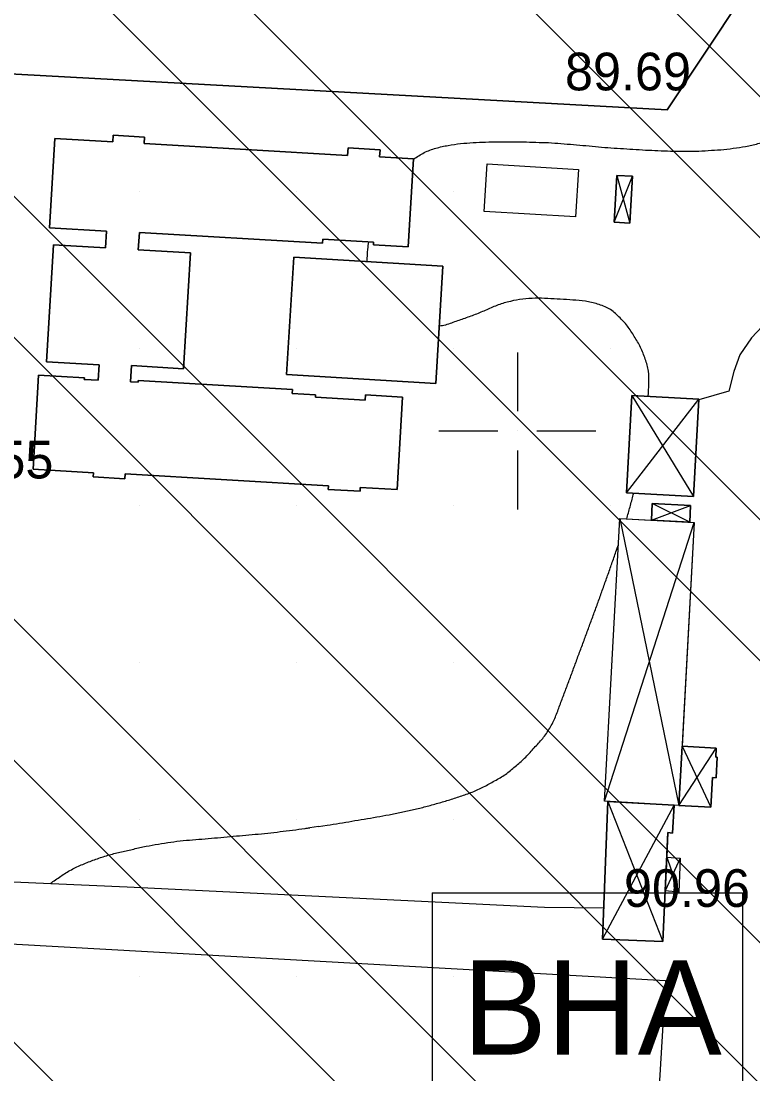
# Model space of a CAD drawing. Extents: x 417995 to 421451, y 4454518 to 4458015.
# Drawn here: x 420920.9 to 421037.5, y 4455397.6 to 4455565.3 of the extents above; entities that cross this region are included whole.
import ezdxf

# ---------------------------------------------------------------- set-up
doc = ezdxf.new("R2010")
doc.units = 0
for name, color, linetype in [('ADAKENARI', 7, 'Continuous'), ('B_Betonzemin', 7, 'Continuous'), ('B_Sundurma', 7, 'Continuous'), ('B_Ticari', 7, 'Continuous'), ('Egri_1m', 7, 'Continuous'), ('P_Grid', 7, 'Continuous'), ('PL_K_BHA', 7, 'Continuous'), ('PL_SAY_KULTUR_TESIS', 7, 'Continuous'), ('SEMBOL_FAT', 7, 'Continuous'), ('SN_TR_SIVILASMA', 7, 'Continuous'), ('TRFAT_BHA', 7, 'Continuous'), ('Y_Kot_Noktasi', 7, 'Continuous')]:
    doc.layers.add(name, color=color, linetype=linetype)

msp = doc.modelspace()

# ---------------------------------------------------------------- linework, layer by layer
at = {"layer": 'ADAKENARI'}
for p, q in [((421023.86, 4455551.11), (421062.73, 4455609.79)), ((420910.3, 4455557.31), (421023.86, 4455551.11))]:
    msp.add_line(p, q, dxfattribs=at)
at = {"layer": 'B_Betonzemin'}
for points in [[(421095.31, 4455422.46), (421065.35, 4455422.26), (421044.81, 4455422.44), (421046.68, 4455456.53), (421048.17, 4455479.85), (421049.52, 4455500.17), (421050.69, 4455507.83), (421055.38, 4455517.65), (421063.57, 4455528.36), (421074.27, 4455541.53), (421066.68, 4455548.25), (421047.77, 4455525.92), (421037.29, 4455514.83), (421035.41, 4455512.12), (421034.49, 4455509.46), (421033.69, 4455506.32), (421028.89, 4455504.93)], [(420995.2, 4455542.55), (421009.72, 4455541.64), (421009.24, 4455534.06), (420994.72, 4455534.96), (420995.2, 4455542.55)], [(420901, 4455380.01), (420934.43, 4455378.05), (420936.03, 4455378.69), (420936.55, 4455379.4), (420936.66, 4455380.27), (420936.46, 4455381.12), (420936.06, 4455381.79), (420935.35, 4455382.61), (420934.47, 4455382.85), (420932.54, 4455383.01), (420905.31, 4455384.24), (420907.36, 4455422.42), (420907.52, 4455428.73), (420937.87, 4455427.42), (421004.34, 4455424.16), (421013.77, 4455424.08)]]:
    msp.add_lwpolyline(points, dxfattribs=at)
at = {"layer": 'B_Sundurma'}
for p, q in [((421015.4, 4455533.24), (421018.35, 4455540.55)), ((421015.82, 4455540.69), (421017.94, 4455533.1)), ((421017.36, 4455490.13), (421028.9, 4455505.06)), ((421018.22, 4455505.65), (421028.04, 4455489.54)), ((421021.35, 4455485.78), (421027.6, 4455488.13)), ((421027.46, 4455485.45), (421021.49, 4455488.46)), ((421016.32, 4455486.05), (421025.73, 4455440.39)), ((421013.9, 4455441.03), (421028.14, 4455485.41)), ((421025.73, 4455440.39), (421031.68, 4455449.51)), ((421026.23, 4455449.8), (421030.81, 4455440.12)), ((421013.57, 4455419.1), (421024.96, 4455440.43)), ((421014.43, 4455441), (421023.15, 4455418.72)), ((421025.94, 4455432), (421023.54, 4455426.78)), ((421023.8, 4455432.16), (421025.71, 4455426.59))]:
    msp.add_line(p, q, dxfattribs=at)
for points in [[(421015.82, 4455540.69), (421015.4, 4455533.24), (421017.94, 4455533.1), (421018.35, 4455540.55)], [(421015.82, 4455540.69), (421018.35, 4455540.55), (421017.94, 4455533.1), (421015.4, 4455533.24)], [(421018.22, 4455505.65), (421017.36, 4455490.13), (421028.04, 4455489.54), (421028.9, 4455505.06)], [(421018.22, 4455505.65), (421028.9, 4455505.06), (421028.04, 4455489.54), (421017.36, 4455490.13)], [(421021.35, 4455485.78), (421027.46, 4455485.45), (421027.6, 4455488.13), (421021.49, 4455488.46)], [(421021.35, 4455485.78), (421021.49, 4455488.46), (421027.6, 4455488.13), (421027.46, 4455485.45)], [(421013.9, 4455441.03), (421016.32, 4455486.05), (421028.14, 4455485.41), (421025.73, 4455440.39)], [(421021.35, 4455485.78), (421027.46, 4455485.45), (421028.14, 4455485.41), (421026.24, 4455449.8), (421025.73, 4455440.39), (421024.96, 4455440.43), (421014.43, 4455441), (421013.9, 4455441.03), (421016.32, 4455486.05)], [(421026.23, 4455449.8), (421025.73, 4455440.39), (421030.81, 4455440.12), (421031.06, 4455444.82), (421031.67, 4455444.79), (421031.85, 4455448.07), (421031.61, 4455448.08), (421031.68, 4455449.51)], [(421025.73, 4455440.39), (421026.24, 4455449.8), (421031.68, 4455449.51), (421031.61, 4455448.08), (421031.85, 4455448.07), (421031.67, 4455444.79), (421031.06, 4455444.82), (421030.81, 4455440.12)], [(421014.43, 4455441), (421013.57, 4455419.1), (421023.15, 4455418.72), (421023.99, 4455436.04), (421024.71, 4455435.98), (421024.96, 4455440.43)], [(421024.96, 4455440.43), (421024.71, 4455435.98), (421023.99, 4455436.04), (421023.8, 4455432.16), (421023.54, 4455426.78), (421023.15, 4455418.72), (421013.57, 4455419.1), (421014.43, 4455441)], [(421023.8, 4455432.16), (421025.94, 4455432), (421025.71, 4455426.59), (421023.54, 4455426.78)], [(421023.54, 4455426.78), (421023.8, 4455432.16), (421025.94, 4455432), (421025.71, 4455426.59)]]:
    msp.add_lwpolyline(points, close=True, dxfattribs=at)
at = {"layer": 'B_Ticari'}
for points in [[(420923.73, 4455508.86), (420922.85, 4455493.92), (420932.46, 4455493.35), (420932.42, 4455492.68), (420937.5, 4455492.38), (420937.55, 4455493.17), (420969.92, 4455491.25), (420969.89, 4455490.69), (420974.95, 4455490.39), (420974.98, 4455491.01), (420980.84, 4455490.67), (420981.71, 4455505.39), (420975.79, 4455505.74), (420975.74, 4455504.9), (420967.82, 4455505.37), (420967.84, 4455505.76), (420964.15, 4455505.98), (420964.19, 4455506.6), (420939.6, 4455508.05), (420939.58, 4455507.74), (420938.38, 4455507.81), (420938.53, 4455510.39), (420946.82, 4455509.9), (420947.91, 4455528.35), (420939.62, 4455528.84), (420939.79, 4455531.59), (420968.97, 4455529.87), (420969.01, 4455530.51), (420977.11, 4455530.03), (420977.09, 4455529.64), (420982.62, 4455529.32), (420983.45, 4455543.33), (420978.06, 4455543.65), (420978.13, 4455544.77), (420973.03, 4455545.07), (420972.95, 4455543.83), (420940.57, 4455545.75), (420940.63, 4455546.77), (420935.62, 4455547.07), (420935.56, 4455546.01), (420926.32, 4455546.56), (420925.48, 4455532.32), (420934.56, 4455531.78), (420934.4, 4455529.13), (420926.11, 4455529.62), (420925.01, 4455511.01), (420933.37, 4455510.52), (420933.22, 4455508.06), (420931.01, 4455508.19), (420931.03, 4455508.43)], [(420923.73, 4455508.86), (420931.03, 4455508.43), (420931.01, 4455508.19), (420933.22, 4455508.06), (420933.37, 4455510.52), (420925.01, 4455511.01), (420926.11, 4455529.62), (420934.4, 4455529.13), (420934.56, 4455531.78), (420925.48, 4455532.32), (420926.32, 4455546.56), (420935.56, 4455546.01), (420935.62, 4455547.07), (420940.63, 4455546.77), (420940.57, 4455545.75), (420972.95, 4455543.83), (420973.03, 4455545.07), (420978.13, 4455544.77), (420978.06, 4455543.65), (420983.45, 4455543.33), (420982.62, 4455529.32), (420977.09, 4455529.64), (420977.11, 4455530.03), (420969.01, 4455530.51), (420968.97, 4455529.87), (420939.79, 4455531.59), (420939.62, 4455528.84), (420947.91, 4455528.35), (420946.82, 4455509.9), (420938.53, 4455510.39), (420938.38, 4455507.81), (420939.58, 4455507.74), (420939.6, 4455508.05), (420964.19, 4455506.6), (420964.15, 4455505.98), (420967.84, 4455505.76), (420967.82, 4455505.37), (420975.74, 4455504.9), (420975.79, 4455505.74), (420981.71, 4455505.39), (420980.84, 4455490.67), (420974.98, 4455491.01), (420974.95, 4455490.39), (420969.89, 4455490.69), (420969.92, 4455491.25), (420937.55, 4455493.17), (420937.5, 4455492.38), (420932.42, 4455492.68), (420932.46, 4455493.35), (420922.85, 4455493.92)], [(420988.12, 4455526.21), (420964.37, 4455527.64), (420963.25, 4455508.97), (420987, 4455507.54)], [(420988.12, 4455526.21), (420987, 4455507.54), (420963.25, 4455508.97), (420964.37, 4455527.64)], [(420913.52, 4455418.68), (421023.6, 4455412.5), (421022.26, 4455390.39), (420912.46, 4455396.44)], [(420913.52, 4455418.68), (421023.6, 4455412.5), (421022.26, 4455390.39), (420912.46, 4455396.44)]]:
    msp.add_lwpolyline(points, close=True, dxfattribs=at)
at = {"layer": 'Egri_1m'}
for q in [(420966.95, 4455436.83), (420969.7, 4455437.23)]:
    msp.add_line((420968.32, 4455437.03), q, dxfattribs=at)
for points in [[(420983.44, 4455543.28), (420985.16, 4455544.31), (420987.03, 4455545.02), (420988.98, 4455545.46), (420990.96, 4455545.74), (420992.95, 4455545.9), (420994.95, 4455545.99), (420996.95, 4455546.02), (420998.95, 4455546.03), (421000.95, 4455546.03), (421002.95, 4455545.96), (421004.95, 4455545.9), (421006.94, 4455545.76), (421008.94, 4455545.59), (421010.93, 4455545.42), (421012.92, 4455545.24), (421014.91, 4455545.07), (421016.91, 4455544.94), (421018.91, 4455544.81), (421020.9, 4455544.7), (421022.9, 4455544.61), (421024.9, 4455544.55), (421026.9, 4455544.55), (421028.9, 4455544.56), (421030.9, 4455544.69), (421032.89, 4455544.81), (421034.88, 4455545.07), (421036.85, 4455545.39), (421038.79, 4455545.87), (421040.72, 4455546.4), (421042.6, 4455547.07), (421044.48, 4455547.75), (421046.3, 4455548.59), (421048, 4455549.64), (421049.56, 4455550.89), (421050.94, 4455552.35), (421052.24, 4455553.86), (421053.41, 4455555.48), (421053.99, 4455556.29)], [(420976.09, 4455526.93), (420976.18, 4455528.93), (420976.34, 4455530.08)], [(421020.84, 4455505.51), (421020.95, 4455507.51), (421020.87, 4455509.51), (421020.37, 4455511.44), (421019.62, 4455513.3), (421018.63, 4455515.03), (421017.52, 4455516.7), (421016.17, 4455518.17), (421014.63, 4455519.44), (421012.77, 4455520.2), (421010.83, 4455520.65), (421008.83, 4455520.84), (421006.84, 4455520.97), (421004.84, 4455521.08), (421002.84, 4455521.12), (421000.85, 4455521), (420998.88, 4455520.63), (420996.96, 4455520.07), (420995.12, 4455519.29), (420993.27, 4455518.52), (420991.39, 4455517.84), (420989.51, 4455517.18), (420987.56, 4455516.7), (420987.55, 4455516.7)], [(421017.41, 4455485.99), (421017.95, 4455487.91), (421018.46, 4455489.85), (421018.51, 4455490.07)], [(420969.7, 4455437.23), (420971.67, 4455437.55), (420973.64, 4455437.87), (420975.62, 4455438.2), (420977.59, 4455438.54), (420979.56, 4455438.89), (420981.52, 4455439.29), (420983.47, 4455439.73), (420985.41, 4455440.19), (420987.34, 4455440.73), (420989.26, 4455441.28), (420991.16, 4455441.91), (420993.04, 4455442.6), (420994.85, 4455443.45), (420996.6, 4455444.41), (420998.3, 4455445.47), (420999.84, 4455446.74), (421001.34, 4455448.07), (421002.68, 4455449.55), (421004.03, 4455451.03), (421005.16, 4455452.68), (421006.05, 4455454.47), (421006.77, 4455456.33), (421007.48, 4455458.21), (421008.18, 4455460.08), (421008.88, 4455461.95), (421009.57, 4455463.83), (421010.27, 4455465.7), (421010.96, 4455467.58), (421011.65, 4455469.46), (421012.34, 4455471.33), (421013.03, 4455473.21), (421013.7, 4455475.09), (421014.38, 4455476.98), (421015.04, 4455478.86), (421015.7, 4455480.75), (421016.09, 4455481.88)], [(420925.62, 4455427.95), (420927.26, 4455429.09), (420928.96, 4455430.14), (420930.77, 4455430.99), (420932.63, 4455431.73), (420934.53, 4455432.36), (420936.46, 4455432.88), (420938.41, 4455433.32), (420940.36, 4455433.77), (420942.33, 4455434.13), (420944.3, 4455434.45), (420946.28, 4455434.73), (420948.27, 4455434.9), (420950.26, 4455435.07), (420952.26, 4455435.24), (420954.25, 4455435.42), (420956.24, 4455435.6), (420958.23, 4455435.78), (420960.23, 4455435.96), (420962.21, 4455436.2), (420964.19, 4455436.45), (420966.18, 4455436.72), (420966.95, 4455436.83)]]:
    msp.add_spline(points, degree=3, dxfattribs=at)
at = {"layer": 'P_Grid'}
for p, q in [((421000, 4455512.5), (421000, 4455503.12)), ((420987.5, 4455500), (420996.88, 4455500)), ((421000, 4455500), (421000, 4455500)), ((421003.12, 4455500), (421012.5, 4455500)), ((421000, 4455496.88), (421000, 4455487.5))]:
    msp.add_line(p, q, dxfattribs=at)
at = {"layer": 'PL_K_BHA'}
for p, q in [((421062.73, 4455609.79), (421023.86, 4455551.11)), ((421023.86, 4455551.11), (420910.3, 4455557.31))]:
    msp.add_line(p, q, dxfattribs=at)
at = {"layer": 'PL_SAY_KULTUR_TESIS'}
msp.add_lwpolyline([(421062.73, 4455609.79), (421023.86, 4455551.11), (420910.3, 4455557.31), (420910.45, 4455560.12), (420912.47, 4455594.25)], dxfattribs=at)
at = {"layer": 'SEMBOL_FAT'}
for p, q in [((420986.42, 4455426.47), (420986.42, 4455391.47)), ((420986.42, 4455426.47), (421035.88, 4455426.47)), ((421035.88, 4455426.47), (421035.88, 4455391.47))]:
    msp.add_line(p, q, dxfattribs=at)
at = {"layer": 'SN_TR_SIVILASMA'}
for p, q in [((421269.77, 4455322.09), (420183.63, 4456408.23)), ((421269.54, 4455299.87), (420176.15, 4456393.26)), ((421269.08, 4455255.43), (420161.18, 4456363.33)), ((421268.85, 4455233.21), (420151.38, 4456350.68)), ((421268.38, 4455188.77), (420123.47, 4456333.68)), ((421268.15, 4455166.56), (420116.87, 4456317.84)), ((421267.69, 4455122.12), (420103.66, 4456286.14)), ((421267.46, 4455099.9), (420097.06, 4456270.29)), ((421266.99, 4455055.46), (420083.86, 4456238.6))]:
    msp.add_line(p, q, dxfattribs=at)
at = {"layer": 'TRFAT_BHA'}
for p, q in [((420939.85, 4455538.16), (420939.85, 4455538.16)), ((420964.85, 4455538.16), (420964.85, 4455538.16)), ((420989.85, 4455538.16), (420989.85, 4455538.16)), ((421014.85, 4455538.16), (421014.85, 4455538.16)), ((420939.85, 4455513.16), (420939.85, 4455513.16)), ((420964.85, 4455513.16), (420964.85, 4455513.16)), ((420989.85, 4455513.16), (420989.85, 4455513.16)), ((421014.85, 4455513.16), (421014.85, 4455513.16)), ((420939.85, 4455488.16), (420939.85, 4455488.16)), ((420964.85, 4455488.16), (420964.85, 4455488.16)), ((420989.85, 4455488.16), (420989.85, 4455488.16)), ((421014.85, 4455488.16), (421014.85, 4455488.16)), ((420939.85, 4455463.16), (420939.85, 4455463.16)), ((420964.85, 4455463.16), (420964.85, 4455463.16)), ((420989.85, 4455463.16), (420989.85, 4455463.16)), ((421014.85, 4455463.16), (421014.85, 4455463.16)), ((420939.85, 4455438.16), (420939.85, 4455438.16)), ((420964.85, 4455438.16), (420964.85, 4455438.16)), ((420989.85, 4455438.16), (420989.85, 4455438.16)), ((421014.85, 4455438.16), (421014.85, 4455438.16)), ((420939.85, 4455413.16), (420939.85, 4455413.16)), ((420964.85, 4455413.16), (420964.85, 4455413.16)), ((420989.85, 4455413.16), (420989.85, 4455413.16)), ((421014.85, 4455413.16), (421014.85, 4455413.16))]:
    msp.add_line(p, q, dxfattribs=at)

# ---------------------------------------------------------------- texts
at = {"layer": 'SEMBOL_FAT'}
msp.add_text('BHA', height=15, dxfattribs=at).set_placement((420991.31, 4455400.7))
at = {"layer": 'Y_Kot_Noktasi'}
for s, p in [('89.69', (421007.58, 4455554.22)), ('89.55', (420906.02, 4455492.43)), ('90.96', (421016.98, 4455424.22))]:
    msp.add_text(s, height=6, dxfattribs=at).set_placement(p)

doc.saveas('drawing.dxf')
